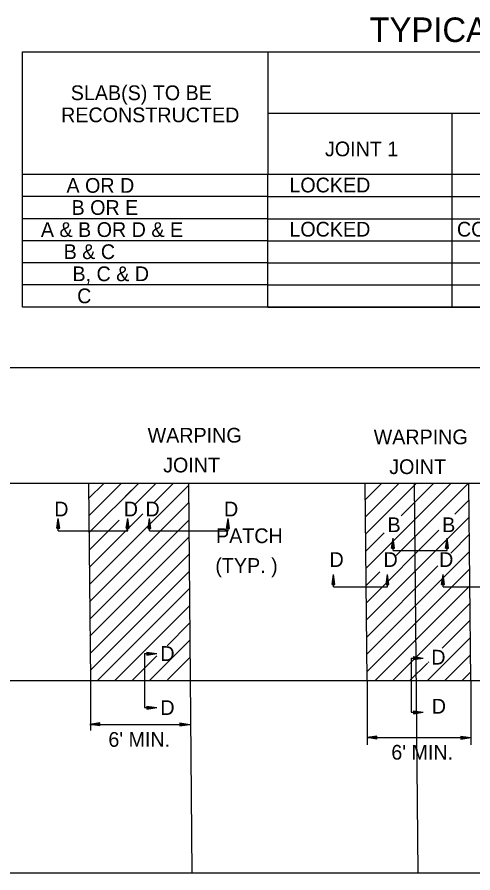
# Model space of a CAD drawing. Extents: x 1375738 to 1375905, y 380661 to 380875.
# Drawn here: x 1375810.09 to 1375824.96, y 380818.56 to 380846.45 of the extents above; entities that cross this region are included whole.
import ezdxf

# ---------------------------------------------------------------- set-up
doc = ezdxf.new("R2010")
doc.units = 0
doc.layers.add('R_Border', color=7, linetype='Continuous')
doc.layers.add('R_Draft', color=7, linetype='Continuous')

msp = doc.modelspace()

# ---------------------------------------------------------------- linework, layer by layer
at = {"layer": 'R_Border'}
msp.add_line((1375786.095, 380835.027), (1375854.78, 380835.027), dxfattribs=at)
at = {"layer": 'R_Draft'}
for p, q in [((1375810.272, 380837), (1375810.272, 380845.32)), ((1375810.272, 380845.32), (1375854.272, 380845.32)), ((1375818.272, 380845.32), (1375818.272, 380841.32)), ((1375818.272, 380843.319), (1375854.272, 380843.319)), ((1375824.272, 380843.319), (1375824.272, 380841.32)), ((1375818.272, 380841.32), (1375810.272, 380841.32)), ((1375824.272, 380841.32), (1375818.272, 380841.32)), ((1375818.272, 380840.6), (1375818.272, 380841.32)), ((1375830.272, 380841.32), (1375824.272, 380841.32)), ((1375824.272, 380841.32), (1375824.272, 380840.6)), ((1375818.272, 380840.6), (1375810.272, 380840.6)), ((1375818.272, 380840.6), (1375824.272, 380840.6)), ((1375818.272, 380839.88), (1375818.272, 380840.6)), ((1375824.272, 380840.6), (1375824.272, 380839.88)), ((1375824.272, 380840.6), (1375830.272, 380840.6)), ((1375818.272, 380839.88), (1375810.272, 380839.88)), ((1375818.272, 380839.88), (1375824.272, 380839.88)), ((1375818.272, 380839.16), (1375818.272, 380839.88)), ((1375824.272, 380839.88), (1375824.272, 380839.16)), ((1375824.272, 380839.88), (1375830.272, 380839.88)), ((1375818.272, 380839.16), (1375810.272, 380839.16)), ((1375818.272, 380839.16), (1375824.272, 380839.16)), ((1375818.272, 380838.44), (1375818.272, 380839.16)), ((1375824.272, 380839.16), (1375824.272, 380838.44)), ((1375824.272, 380839.16), (1375830.272, 380839.16)), ((1375818.272, 380838.44), (1375810.272, 380838.44)), ((1375818.272, 380838.44), (1375824.272, 380838.44)), ((1375818.272, 380837.72), (1375818.272, 380838.44)), ((1375824.272, 380838.44), (1375824.272, 380837.72)), ((1375824.272, 380838.44), (1375830.272, 380838.44)), ((1375818.272, 380837.72), (1375810.272, 380837.72)), ((1375818.272, 380837.72), (1375824.272, 380837.72)), ((1375818.272, 380837), (1375818.272, 380837.72)), ((1375824.272, 380837.72), (1375824.272, 380837)), ((1375824.272, 380837.72), (1375830.272, 380837.72)), ((1375854.272, 380837), (1375810.272, 380837)), ((1375818.272, 380837), (1375810.272, 380837)), ((1375818.272, 380837), (1375824.272, 380837)), ((1375824.272, 380837), (1375830.272, 380837)), ((1375795.429, 380831.261), (1375839.429, 380831.261)), ((1375812.423, 380831.262), (1375812.484, 380824.829)), ((1375812.427, 380830.759), (1375812.929, 380831.261)), ((1375812.433, 380830.199), (1375813.494, 380831.261)), ((1375814.061, 380831.261), (1375812.438, 380829.639)), ((1375814.06, 380831.261), (1375813.622, 380830.823)), ((1375813.952, 380830.587), (1375814.625, 380831.261)), ((1375814.552, 380830.622), (1375815.191, 380831.261)), ((1375815.678, 380831.261), (1375815.796, 380818.564)), ((1375821.51, 380824.829), (1375821.449, 380831.245)), ((1375821.454, 380830.731), (1375821.984, 380831.261)), ((1375821.459, 380830.17), (1375822.549, 380831.261)), ((1375821.465, 380829.61), (1375823.115, 380831.261)), ((1375821.475, 380828.489), (1375824.246, 380831.261)), ((1375822.458, 380828.905), (1375824.813, 380831.261)), ((1375822.623, 380830.203), (1375823.681, 380831.261)), ((1375823.169, 380818.564), (1375823.049, 380831.261)), ((1375824.889, 380824.829), (1375824.827, 380831.261)), ((1375812.454, 380827.957), (1375815.679, 380831.182)), ((1375815.139, 380830.642), (1375815.678, 380831.181)), ((1375824.369, 380830.251), (1375824.833, 380830.715)), ((1375812.459, 380827.397), (1375815.683, 380830.621)), ((1375812.449, 380828.518), (1375814.194, 380830.263)), ((1375821.491, 380826.808), (1375824.838, 380830.155)), ((1375811.388, 380829.791), (1375811.436, 380830.111)), ((1375811.396, 380829.791), (1375811.436, 380830.057)), ((1375811.404, 380829.791), (1375811.436, 380830.002)), ((1375811.412, 380829.791), (1375811.436, 380829.949)), ((1375811.42, 380829.791), (1375811.436, 380829.895)), ((1375811.436, 380829.711), (1375811.436, 380830.111)), ((1375811.484, 380829.791), (1375811.436, 380830.111)), ((1375811.476, 380829.791), (1375811.436, 380830.057)), ((1375811.468, 380829.791), (1375811.436, 380830.002)), ((1375811.46, 380829.791), (1375811.436, 380829.949)), ((1375811.451, 380829.791), (1375811.436, 380829.895)), ((1375812.443, 380829.079), (1375813.425, 380830.06)), ((1375812.465, 380826.835), (1375815.689, 380830.061)), ((1375813.654, 380829.791), (1375813.702, 380830.111)), ((1375813.662, 380829.791), (1375813.702, 380830.057)), ((1375813.67, 380829.791), (1375813.702, 380830.002)), ((1375813.678, 380829.791), (1375813.702, 380829.949)), ((1375813.687, 380829.791), (1375813.702, 380829.895)), ((1375813.702, 380829.711), (1375813.702, 380830.111)), ((1375813.75, 380829.791), (1375813.702, 380830.111)), ((1375813.742, 380829.791), (1375813.702, 380830.057)), ((1375813.734, 380829.791), (1375813.702, 380830.002)), ((1375813.726, 380829.791), (1375813.702, 380829.949)), ((1375813.718, 380829.791), (1375813.702, 380829.895)), ((1375814.363, 380829.789), (1375814.411, 380830.109)), ((1375814.371, 380829.789), (1375814.411, 380830.055)), ((1375814.379, 380829.789), (1375814.411, 380830.001)), ((1375814.387, 380829.789), (1375814.411, 380829.947)), ((1375814.395, 380829.789), (1375814.411, 380829.893)), ((1375814.411, 380829.709), (1375814.411, 380830.109)), ((1375814.459, 380829.789), (1375814.411, 380830.109)), ((1375814.451, 380829.789), (1375814.411, 380830.055)), ((1375814.443, 380829.789), (1375814.411, 380830.001)), ((1375814.435, 380829.789), (1375814.411, 380829.947)), ((1375814.426, 380829.789), (1375814.411, 380829.893)), ((1375816.924, 380829.789), (1375816.972, 380830.109)), ((1375816.932, 380829.789), (1375816.972, 380830.055)), ((1375816.94, 380829.789), (1375816.972, 380830.001)), ((1375816.948, 380829.789), (1375816.972, 380829.947)), ((1375816.957, 380829.789), (1375816.972, 380829.893)), ((1375816.972, 380829.709), (1375816.972, 380830.109)), ((1375817.02, 380829.789), (1375816.972, 380830.109)), ((1375817.012, 380829.789), (1375816.972, 380830.055)), ((1375817.004, 380829.789), (1375816.972, 380830.001)), ((1375816.996, 380829.789), (1375816.972, 380829.947)), ((1375816.988, 380829.789), (1375816.972, 380829.893)), ((1375811.388, 380829.791), (1375811.484, 380829.791)), ((1375811.428, 380829.791), (1375811.436, 380829.841)), ((1375811.443, 380829.791), (1375811.436, 380829.841)), ((1375811.436, 380829.711), (1375813.702, 380829.711)), ((1375813.654, 380829.791), (1375813.75, 380829.791)), ((1375813.695, 380829.791), (1375813.702, 380829.841)), ((1375813.71, 380829.791), (1375813.702, 380829.841)), ((1375814.363, 380829.789), (1375814.459, 380829.789)), ((1375814.403, 380829.789), (1375814.411, 380829.839)), ((1375814.418, 380829.789), (1375814.411, 380829.839)), ((1375814.411, 380829.709), (1375816.972, 380829.709)), ((1375816.924, 380829.789), (1375817.02, 380829.789)), ((1375816.965, 380829.789), (1375816.972, 380829.839)), ((1375816.98, 380829.789), (1375816.972, 380829.839)), ((1375821.47, 380829.05), (1375822.069, 380829.649)), ((1375821.486, 380827.368), (1375823.847, 380829.729)), ((1375824.235, 380828.986), (1375824.843, 380829.595)), ((1375812.47, 380826.277), (1375815.694, 380829.501)), ((1375822.307, 380829.148), (1375822.355, 380829.468)), ((1375822.315, 380829.148), (1375822.355, 380829.414)), ((1375822.323, 380829.148), (1375822.355, 380829.359)), ((1375822.331, 380829.148), (1375822.355, 380829.306)), ((1375822.355, 380829.068), (1375822.355, 380829.468)), ((1375822.403, 380829.148), (1375822.355, 380829.468)), ((1375822.395, 380829.148), (1375822.355, 380829.414)), ((1375822.387, 380829.148), (1375822.355, 380829.359)), ((1375822.379, 380829.148), (1375822.355, 380829.306)), ((1375824.068, 380829.148), (1375824.116, 380829.468)), ((1375824.076, 380829.148), (1375824.116, 380829.414)), ((1375824.084, 380829.148), (1375824.116, 380829.359)), ((1375824.092, 380829.148), (1375824.116, 380829.306)), ((1375824.116, 380829.068), (1375824.116, 380829.468)), ((1375824.164, 380829.148), (1375824.116, 380829.468)), ((1375824.156, 380829.148), (1375824.116, 380829.414)), ((1375824.148, 380829.148), (1375824.116, 380829.359)), ((1375824.14, 380829.148), (1375824.116, 380829.306)), ((1375821.502, 380825.687), (1375824.849, 380829.034)), ((1375822.307, 380829.148), (1375822.403, 380829.148)), ((1375822.339, 380829.148), (1375822.355, 380829.252)), ((1375822.347, 380829.148), (1375822.355, 380829.198)), ((1375822.37, 380829.148), (1375822.355, 380829.252)), ((1375822.362, 380829.148), (1375822.355, 380829.198)), ((1375822.355, 380829.068), (1375824.116, 380829.068)), ((1375824.068, 380829.148), (1375824.164, 380829.148)), ((1375824.101, 380829.148), (1375824.116, 380829.252)), ((1375824.109, 380829.148), (1375824.116, 380829.198)), ((1375824.132, 380829.148), (1375824.116, 380829.252)), ((1375824.124, 380829.148), (1375824.116, 380829.198)), ((1375812.475, 380825.716), (1375815.699, 380828.94)), ((1375821.496, 380826.247), (1375823.818, 380828.569)), ((1375821.507, 380825.127), (1375824.854, 380828.474)), ((1375812.481, 380825.158), (1375815.705, 380828.382)), ((1375820.363, 380827.963), (1375820.411, 380828.283)), ((1375820.371, 380827.963), (1375820.411, 380828.229)), ((1375820.379, 380827.963), (1375820.411, 380828.175)), ((1375820.411, 380827.883), (1375820.411, 380828.283)), ((1375820.459, 380827.963), (1375820.411, 380828.283)), ((1375820.451, 380827.963), (1375820.411, 380828.229)), ((1375820.443, 380827.963), (1375820.411, 380828.175)), ((1375821.481, 380827.929), (1375821.925, 380828.373)), ((1375822.124, 380827.963), (1375822.172, 380828.283)), ((1375822.132, 380827.963), (1375822.172, 380828.229)), ((1375822.14, 380827.963), (1375822.172, 380828.175)), ((1375822.172, 380827.883), (1375822.172, 380828.283)), ((1375822.22, 380827.963), (1375822.172, 380828.283)), ((1375822.212, 380827.963), (1375822.172, 380828.229)), ((1375822.204, 380827.963), (1375822.172, 380828.175)), ((1375823.937, 380827.963), (1375823.985, 380828.283)), ((1375823.945, 380827.963), (1375823.985, 380828.229)), ((1375823.953, 380827.963), (1375823.985, 380828.175)), ((1375823.985, 380827.883), (1375823.985, 380828.283)), ((1375824.033, 380827.963), (1375823.985, 380828.283)), ((1375824.025, 380827.963), (1375823.985, 380828.229)), ((1375824.017, 380827.963), (1375823.985, 380828.175)), ((1375820.363, 380827.963), (1375820.459, 380827.963)), ((1375820.387, 380827.963), (1375820.411, 380828.121)), ((1375820.395, 380827.963), (1375820.411, 380828.067)), ((1375820.403, 380827.963), (1375820.411, 380828.013)), ((1375820.435, 380827.963), (1375820.411, 380828.121)), ((1375820.426, 380827.963), (1375820.411, 380828.067)), ((1375820.418, 380827.963), (1375820.411, 380828.013)), ((1375821.775, 380824.829), (1375824.859, 380827.914)), ((1375822.124, 380827.963), (1375822.22, 380827.963)), ((1375822.148, 380827.963), (1375822.172, 380828.121)), ((1375822.157, 380827.963), (1375822.172, 380828.067)), ((1375822.165, 380827.963), (1375822.172, 380828.013)), ((1375822.196, 380827.963), (1375822.172, 380828.121)), ((1375822.188, 380827.963), (1375822.172, 380828.067)), ((1375822.18, 380827.963), (1375822.172, 380828.013)), ((1375823.937, 380827.963), (1375824.033, 380827.963)), ((1375823.961, 380827.963), (1375823.985, 380828.121)), ((1375823.969, 380827.963), (1375823.985, 380828.067)), ((1375823.977, 380827.963), (1375823.985, 380828.013)), ((1375824.009, 380827.963), (1375823.985, 380828.121)), ((1375824.001, 380827.963), (1375823.985, 380828.067)), ((1375823.993, 380827.963), (1375823.985, 380828.013)), ((1375812.718, 380824.829), (1375815.71, 380827.821)), ((1375820.411, 380827.883), (1375822.172, 380827.883)), ((1375823.985, 380827.883), (1375825.747, 380827.883)), ((1375822.341, 380824.829), (1375824.865, 380827.354)), ((1375813.284, 380824.829), (1375815.715, 380827.261)), ((1375823.958, 380825.881), (1375824.87, 380826.793)), ((1375814.987, 380825.967), (1375815.721, 380826.701)), ((1375823.472, 380824.829), (1375824.875, 380826.233)), ((1375814.414, 380824.829), (1375815.726, 380826.142)), ((1375814.248, 380825.711), (1375814.248, 380823.949)), ((1375814.248, 380825.711), (1375814.648, 380825.711)), ((1375814.328, 380825.759), (1375814.648, 380825.711)), ((1375814.328, 380825.759), (1375814.328, 380825.663)), ((1375814.328, 380825.751), (1375814.594, 380825.711)), ((1375814.328, 380825.743), (1375814.539, 380825.711)), ((1375814.328, 380825.735), (1375814.486, 380825.711)), ((1375814.328, 380825.727), (1375814.432, 380825.711)), ((1375814.328, 380825.719), (1375814.378, 380825.711)), ((1375814.328, 380825.663), (1375814.648, 380825.711)), ((1375814.328, 380825.695), (1375814.432, 380825.711)), ((1375814.328, 380825.679), (1375814.539, 380825.711)), ((1375814.328, 380825.671), (1375814.594, 380825.711)), ((1375814.328, 380825.687), (1375814.486, 380825.711)), ((1375814.328, 380825.703), (1375814.378, 380825.711)), ((1375824.038, 380824.829), (1375824.881, 380825.672)), ((1375813.849, 380824.829), (1375814.654, 380825.633)), ((1375815, 380824.85), (1375815.731, 380825.582)), ((1375822.906, 380824.829), (1375823.478, 380825.401)), ((1375822.94, 380825.561), (1375822.94, 380823.799)), ((1375822.94, 380825.561), (1375823.34, 380825.561)), ((1375823.02, 380825.609), (1375823.34, 380825.561)), ((1375823.02, 380825.609), (1375823.02, 380825.513)), ((1375823.02, 380825.601), (1375823.286, 380825.561)), ((1375823.02, 380825.593), (1375823.231, 380825.561)), ((1375823.02, 380825.585), (1375823.178, 380825.561)), ((1375823.02, 380825.577), (1375823.124, 380825.561)), ((1375823.02, 380825.569), (1375823.07, 380825.561)), ((1375823.02, 380825.513), (1375823.34, 380825.561)), ((1375823.02, 380825.545), (1375823.124, 380825.561)), ((1375823.02, 380825.529), (1375823.231, 380825.561)), ((1375823.02, 380825.521), (1375823.286, 380825.561)), ((1375823.02, 380825.537), (1375823.178, 380825.561)), ((1375823.02, 380825.553), (1375823.07, 380825.561)), ((1375823.499, 380825.422), (1375823.52, 380825.443)), ((1375824.604, 380824.829), (1375824.886, 380825.112)), ((1375794.677, 380824.829), (1375839.429, 380824.829)), ((1375806.196, 380824.829), (1375839.375, 380824.829)), ((1375812.484, 380824.829), (1375812.484, 380823.201)), ((1375821.51, 380824.829), (1375821.51, 380822.731)), ((1375824.889, 380824.829), (1375824.889, 380822.731)), ((1375814.328, 380823.997), (1375814.648, 380823.949)), ((1375814.328, 380823.997), (1375814.328, 380823.901)), ((1375814.248, 380823.949), (1375814.648, 380823.949)), ((1375814.328, 380823.989), (1375814.594, 380823.949)), ((1375814.328, 380823.981), (1375814.539, 380823.949)), ((1375814.328, 380823.973), (1375814.486, 380823.949)), ((1375814.328, 380823.965), (1375814.432, 380823.949)), ((1375814.328, 380823.957), (1375814.378, 380823.949)), ((1375814.328, 380823.901), (1375814.648, 380823.949)), ((1375814.328, 380823.934), (1375814.432, 380823.949)), ((1375814.328, 380823.917), (1375814.539, 380823.949)), ((1375814.328, 380823.909), (1375814.594, 380823.949)), ((1375814.328, 380823.925), (1375814.486, 380823.949)), ((1375814.328, 380823.942), (1375814.378, 380823.949)), ((1375822.94, 380823.799), (1375823.34, 380823.799)), ((1375823.02, 380823.847), (1375823.34, 380823.799)), ((1375823.02, 380823.847), (1375823.02, 380823.751)), ((1375823.02, 380823.839), (1375823.286, 380823.799)), ((1375823.02, 380823.831), (1375823.231, 380823.799)), ((1375823.02, 380823.823), (1375823.178, 380823.799)), ((1375823.02, 380823.815), (1375823.124, 380823.799)), ((1375823.02, 380823.807), (1375823.07, 380823.799)), ((1375823.02, 380823.751), (1375823.34, 380823.799)), ((1375823.02, 380823.784), (1375823.124, 380823.799)), ((1375823.02, 380823.767), (1375823.231, 380823.799)), ((1375823.02, 380823.759), (1375823.286, 380823.799)), ((1375823.02, 380823.775), (1375823.178, 380823.799)), ((1375823.02, 380823.792), (1375823.07, 380823.799)), ((1375812.79, 380823.449), (1375812.47, 380823.401)), ((1375812.79, 380823.441), (1375812.524, 380823.401)), ((1375812.79, 380823.353), (1375812.79, 380823.449)), ((1375815.405, 380823.449), (1375815.725, 380823.401)), ((1375815.405, 380823.449), (1375815.405, 380823.353)), ((1375815.405, 380823.441), (1375815.671, 380823.401)), ((1375812.47, 380823.401), (1375815.725, 380823.401)), ((1375812.79, 380823.353), (1375812.47, 380823.401)), ((1375812.79, 380823.361), (1375812.524, 380823.401)), ((1375812.79, 380823.433), (1375812.579, 380823.401)), ((1375812.79, 380823.369), (1375812.579, 380823.401)), ((1375812.79, 380823.425), (1375812.632, 380823.401)), ((1375812.79, 380823.377), (1375812.632, 380823.401)), ((1375812.79, 380823.417), (1375812.686, 380823.401)), ((1375812.79, 380823.385), (1375812.686, 380823.401)), ((1375812.79, 380823.409), (1375812.74, 380823.401)), ((1375812.79, 380823.393), (1375812.74, 380823.401)), ((1375815.405, 380823.433), (1375815.616, 380823.401)), ((1375815.405, 380823.425), (1375815.563, 380823.401)), ((1375815.405, 380823.417), (1375815.509, 380823.401)), ((1375815.405, 380823.409), (1375815.455, 380823.401)), ((1375815.405, 380823.353), (1375815.725, 380823.401)), ((1375815.405, 380823.385), (1375815.509, 380823.401)), ((1375815.405, 380823.369), (1375815.616, 380823.401)), ((1375815.405, 380823.361), (1375815.671, 380823.401)), ((1375815.405, 380823.377), (1375815.563, 380823.401)), ((1375815.405, 380823.393), (1375815.455, 380823.401)), ((1375821.83, 380823.022), (1375821.51, 380822.974)), ((1375821.51, 380822.974), (1375824.889, 380822.974)), ((1375821.83, 380822.926), (1375821.51, 380822.974)), ((1375821.83, 380823.014), (1375821.563, 380822.974)), ((1375821.83, 380822.934), (1375821.563, 380822.974)), ((1375821.83, 380823.006), (1375821.618, 380822.974)), ((1375821.83, 380822.942), (1375821.618, 380822.974)), ((1375821.83, 380822.998), (1375821.671, 380822.974)), ((1375821.83, 380822.95), (1375821.671, 380822.974)), ((1375821.83, 380822.99), (1375821.726, 380822.974)), ((1375821.83, 380822.959), (1375821.726, 380822.974)), ((1375821.83, 380822.982), (1375821.779, 380822.974)), ((1375821.83, 380822.967), (1375821.779, 380822.974)), ((1375821.83, 380822.926), (1375821.83, 380823.022)), ((1375824.569, 380823.022), (1375824.889, 380822.974)), ((1375824.569, 380823.022), (1375824.569, 380822.926)), ((1375824.569, 380823.014), (1375824.835, 380822.974)), ((1375824.569, 380823.006), (1375824.781, 380822.974)), ((1375824.569, 380822.998), (1375824.727, 380822.974)), ((1375824.569, 380822.99), (1375824.673, 380822.974)), ((1375824.569, 380822.982), (1375824.619, 380822.974)), ((1375824.569, 380822.926), (1375824.889, 380822.974)), ((1375824.569, 380822.959), (1375824.673, 380822.974)), ((1375824.569, 380822.942), (1375824.781, 380822.974)), ((1375824.569, 380822.934), (1375824.835, 380822.974)), ((1375824.569, 380822.95), (1375824.727, 380822.974)), ((1375824.569, 380822.967), (1375824.619, 380822.974)), ((1375795.429, 380818.564), (1375839.223, 380818.564))]:
    msp.add_line(p, q, dxfattribs=at)

# ---------------------------------------------------------------- texts
for s, height, p in [('TYPICAL SLAB REPLACEMENT EXAMPLES', 0.7996, (1375821.587, 380845.636)), ('SLAB(S) TO BE', 0.48, (1375811.844, 380843.742)), ('RECONSTRUCTED', 0.48, (1375811.529, 380843.022)), ('JOINT 1', 0.48, (1375820.134, 380841.913)), ('     A OR D     ', 0.48, (1375810.812, 380840.724)), ('   LOCKED  ', 0.48, (1375818.438, 380840.737)), ('     B OR E     ', 0.48, (1375810.978, 380840.004)), (' A & B OR D & E ', 0.48, (1375810.691, 380839.284)), ('   LOCKED  ', 0.48, (1375818.438, 380839.297)), ('CONTRACTION', 0.48, (1375824.438, 380839.297)), ('     B & C      ', 0.48, (1375810.721, 380838.564)), ('    B, C & D    ', 0.48, (1375811.186, 380837.844)), ('       C        ', 0.48, (1375810.804, 380837.124)), ('WARPING', 0.48, (1375814.35, 380832.584)), ('WARPING', 0.48, (1375821.722, 380832.529)), ('JOINT', 0.48, (1375814.857, 380831.613)), ('JOINT', 0.48, (1375822.229, 380831.559)), ('D', 0.48, (1375811.306, 380830.179)), ('D', 0.48, (1375813.572, 380830.179)), ('D', 0.48, (1375814.281, 380830.179)), ('D', 0.48, (1375816.842, 380830.179)), ('B', 0.48, (1375822.172, 380829.667)), ('B', 0.48, (1375823.956, 380829.667)), ('PATCH', 0.48, (1375816.581, 380829.309)), ('D', 0.48, (1375820.281, 380828.532)), ('D', 0.48, (1375822.042, 380828.532)), ('D', 0.48, (1375823.855, 380828.532)), ('(TYP. )', 0.48, (1375816.559, 380828.339)), ('D', 0.48, (1375814.766, 380825.471)), ('D', 0.48, (1375823.601, 380825.352)), ('D', 0.48, (1375814.766, 380823.709)), ('D', 0.48, (1375823.616, 380823.754)), ("6' MIN.", 0.48, (1375813.071, 380822.671)), ("6' MIN.", 0.48, (1375822.297, 380822.254))]:
    msp.add_text(s, height=height, dxfattribs=at).set_placement(p)

doc.saveas('drawing.dxf')
